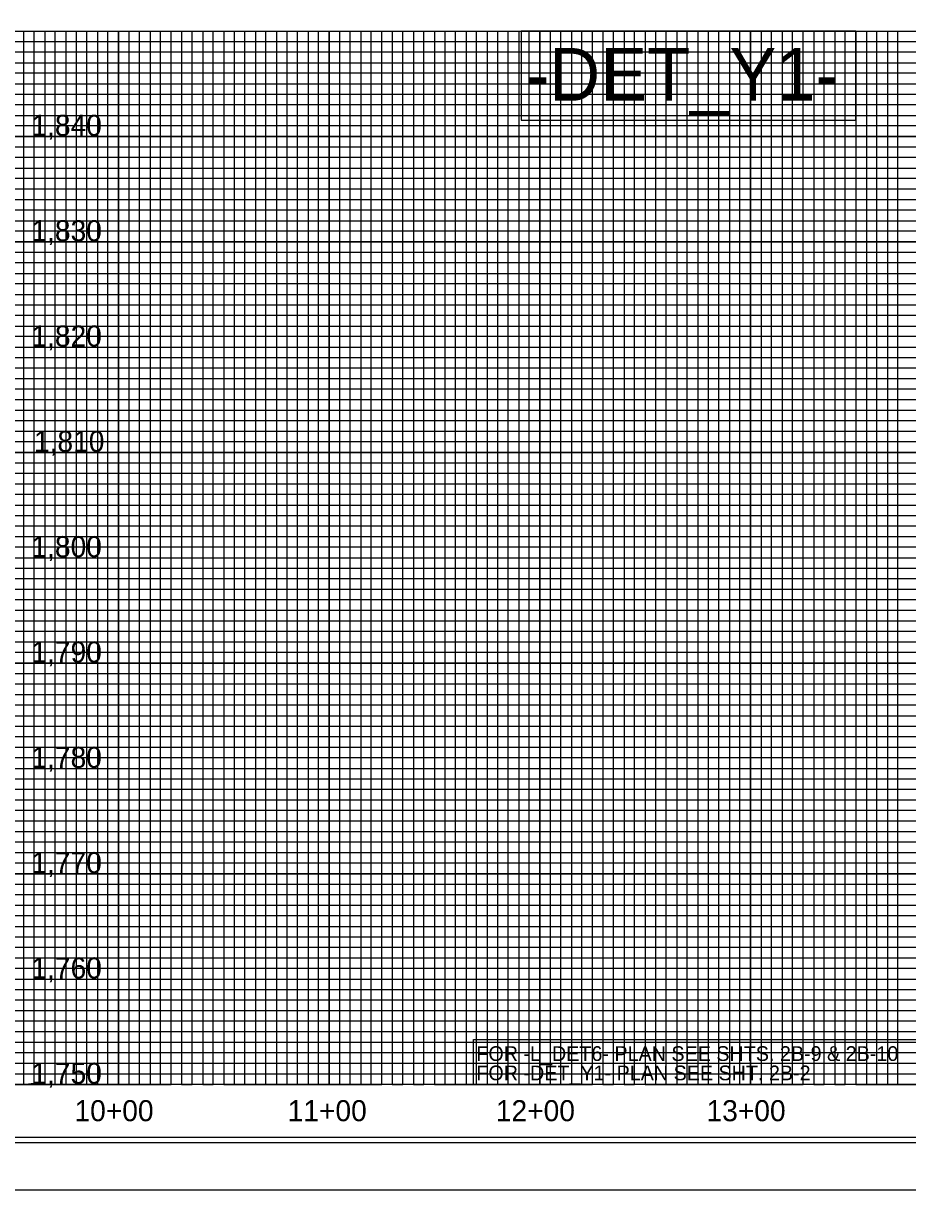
# Model space of a CAD drawing. Extents: x 497599 to 513368, y 404140 to 482942.
# Drawn here: x 506714 to 507133, y 438761 to 439315 of the extents above; entities that cross this region are included whole.
import ezdxf

# ---------------------------------------------------------------- set-up
doc = ezdxf.new("R2010")
doc.units = 0
for name, color, linetype in [('Exist Vertical Profile Vertical Axis Label', 7, 'Continuous'), ('Old_Level_1', 7, 'Continuous'), ('Prop Grid Mask', 7, 'Continuous'), ('Sheet Cutting Line CELL', 7, 'Continuous'), ('Sheet Data Field CELL', 7, 'Continuous'), ('Sheet DOT Grid CELL', 7, 'Continuous'), ('Sheet Layout Profile Border Port 2', 7, 'Continuous'), ('Sheet Plot Border Inside CELL', 7, 'Continuous'), ('Sheet Plot Border Outside CELL', 7, 'Continuous'), ('Sheet Profile CELL', 7, 'Continuous'), ('Sheet Profile Grid Major CELL', 7, 'Continuous'), ('Sheet Profile Grid Middle CELL', 7, 'Continuous'), ('Sheet Profile Grid Minor CELL', 7, 'Continuous')]:
    doc.layers.add(name, color=color, linetype=linetype)

msp = doc.modelspace()

# ---------------------------------------------------------------- linework, layer by layer
at = {"layer": 'Prop Grid Mask'}
for points in [[(507108.68, 439311.14), (506949.82, 439311.14), (506949.82, 439268.82), (507108.68, 439268.82)], [(506927.29, 438832.43), (507138.12, 438832.43), (507138.12, 438811.14), (506927.29, 438811.14)]]:
    msp.add_lwpolyline(points, close=True, dxfattribs=at)
at = {"layer": 'Sheet Cutting Line CELL'}
msp.add_line((505691.68, 438761.14), (507375.68, 438761.14), dxfattribs=at)
at = {"layer": 'Sheet DOT Grid CELL'}
for p, q in [((505858.68, 439311.14), (507358.56, 439311.14)), ((506758.68, 439311.14), (506758.68, 438811.14)), ((506808.68, 439311.14), (506808.68, 438811.14)), ((506858.68, 439311.14), (506858.68, 438811.14)), ((506908.68, 439311.14), (506908.68, 438811.14)), ((506958.68, 439311.14), (506958.68, 438811.14)), ((507008.68, 439311.14), (507008.68, 438811.14)), ((507058.68, 439311.14), (507058.68, 438811.14)), ((507108.68, 439311.14), (507108.68, 438811.14)), ((505858.68, 439261.14), (507358.56, 439261.14)), ((505858.68, 439211.14), (507358.56, 439211.14)), ((505858.68, 439161.14), (507358.56, 439161.14)), ((505858.68, 439111.14), (507358.56, 439111.14)), ((505858.68, 439061.14), (507358.56, 439061.14)), ((505858.68, 439011.14), (507358.56, 439011.14)), ((505858.68, 438961.14), (507358.56, 438961.14)), ((505858.68, 438911.14), (507358.56, 438911.14)), ((505858.68, 438861.14), (507358.56, 438861.14))]:
    msp.add_line(p, q, dxfattribs=at)
at = {"layer": 'Sheet Layout Profile Border Port 2'}
msp.add_lwpolyline([(506758.68, 439311.14), (507308.68, 439311.14), (507308.68, 438811.14), (506758.68, 438811.14)], close=True, dxfattribs=at)
at = {"layer": 'Sheet Plot Border Inside CELL'}
msp.add_lwpolyline([(505704.68, 438783.59), (507371.18, 438783.59), (507371.18, 439838.69), (505704.68, 439838.69)], close=True, dxfattribs=at)
at = {"layer": 'Sheet Plot Border Outside CELL'}
msp.add_lwpolyline([(505691.68, 438761.14), (507375.68, 438761.14), (507375.68, 439861.14), (505691.68, 439861.14)], close=True, dxfattribs=at)
at = {"layer": 'Sheet Profile CELL'}
for p, q in [((505858.68, 439311.14), (507358.68, 439311.14)), ((507358.68, 438811.14), (505858.68, 438811.14)), ((505858.68, 438786.14), (507358.68, 438786.14))]:
    msp.add_line(p, q, dxfattribs=at)
msp.add_lwpolyline([(507358.68, 439836.14), (505858.68, 439836.14), (505858.68, 438786.14), (507358.68, 438786.14)], close=True, dxfattribs=at)
at = {"layer": 'Sheet Profile Grid Major CELL'}
for p, q in [((506758.68, 439311.14), (506808.68, 439311.14)), ((506758.68, 439311.14), (506808.68, 439311.14)), ((506858.68, 439311.14), (506908.68, 439311.14)), ((506858.68, 439311.14), (506908.68, 439311.14)), ((506958.68, 439311.14), (507008.68, 439311.14)), ((506958.68, 439311.14), (507008.68, 439311.14)), ((507058.68, 439311.14), (507108.68, 439311.14)), ((507058.68, 439311.14), (507108.68, 439311.14)), ((507052.65, 438811.14), (507052.65, 438811.14))]:
    msp.add_line(p, q, dxfattribs=at)
for points in [[(506708.68, 438811.14), (506758.68, 438811.14), (506758.68, 439311.14), (506808.68, 439311.14), (506808.68, 438811.14), (506858.68, 438811.14), (506858.68, 439311.14), (506908.68, 439311.14), (506908.68, 438811.14), (506958.68, 438811.14), (506958.68, 439311.14), (507008.68, 439311.14), (507008.68, 438811.14), (507058.68, 438811.14), (507058.68, 439311.14), (507108.68, 439311.14), (507108.68, 438811.14), (507158.68, 438811.14)], [(507358.68, 439261.14), (505858.68, 439261.14)], [(507358.68, 439211.14), (505858.68, 439211.14), (505858.68, 439161.14), (507358.68, 439161.14)], [(507358.68, 439111.14), (505858.68, 439111.14), (505858.68, 439061.14), (507358.68, 439061.14)], [(507358.68, 439011.14), (505858.68, 439011.14), (505858.68, 438961.14), (507358.68, 438961.14)], [(507358.68, 438911.14), (505858.68, 438911.14), (505858.68, 438911.14), (505858.68, 438861.14), (507358.68, 438861.14)], [(507358.68, 438811.14), (505858.68, 438811.14)]]:
    msp.add_lwpolyline(points, dxfattribs=at)
at = {"layer": 'Sheet Profile Grid Middle CELL'}
for points in [[(506683.68, 439311.14), (506733.68, 439311.14), (506733.68, 438811.14), (506783.68, 438811.14), (506783.68, 439311.14), (506833.68, 439311.14), (506833.68, 438811.14), (506883.68, 438811.14), (506883.68, 439311.14), (506933.68, 439311.14), (506933.68, 438811.14), (506983.68, 438811.14), (506983.68, 439311.14), (507033.68, 439311.14), (507033.68, 438811.14), (507083.68, 438811.14), (507083.68, 439311.14), (507133.68, 439311.14)], [(505858.68, 439286.14), (507358.68, 439286.14)], [(507358.68, 439236.14), (505858.68, 439236.14), (505858.68, 439186.14), (507358.68, 439186.14)], [(507358.68, 439136.14), (505858.68, 439136.14), (505858.68, 439086.14), (507358.68, 439086.14)], [(507358.68, 439036.14), (505858.68, 439036.14), (505858.68, 438986.14), (507358.68, 438986.14)], [(507358.68, 438936.14), (505858.68, 438936.14), (505858.68, 438886.14), (507358.68, 438886.14)], [(507358.68, 438836.14), (505858.68, 438836.14)]]:
    msp.add_lwpolyline(points, dxfattribs=at)
at = {"layer": 'Sheet Profile Grid Minor CELL'}
for p, q in [((505908.68, 439306.14), (507308.68, 439306.14)), ((507308.68, 439301.14), (505908.68, 439301.14)), ((505908.68, 439296.14), (507308.68, 439296.14)), ((507308.68, 439291.14), (505908.68, 439291.14)), ((505908.68, 439281.14), (507308.68, 439281.14)), ((507308.68, 439276.14), (505908.68, 439276.14)), ((505908.68, 439271.14), (507308.68, 439271.14)), ((507308.68, 439266.14), (505908.68, 439266.14)), ((505908.68, 439256.14), (507308.68, 439256.14)), ((507308.68, 439251.14), (505908.68, 439251.14)), ((505908.68, 439246.14), (507308.68, 439246.14)), ((507308.68, 439241.14), (505908.68, 439241.14)), ((505908.68, 439231.14), (507308.68, 439231.14)), ((507308.68, 439226.14), (505908.68, 439226.14)), ((505908.68, 439221.14), (507308.68, 439221.14)), ((507308.68, 439216.14), (505908.68, 439216.14)), ((505908.68, 439206.14), (507308.68, 439206.14)), ((507308.68, 439201.14), (505908.68, 439201.14)), ((505908.68, 439196.14), (507308.68, 439196.14)), ((507308.68, 439191.14), (505908.68, 439191.14)), ((505908.68, 439181.14), (507308.68, 439181.14)), ((507308.68, 439176.14), (505908.68, 439176.14)), ((505908.68, 439171.14), (507308.68, 439171.14)), ((507308.68, 439166.14), (505908.68, 439166.14)), ((505908.68, 439156.14), (507308.68, 439156.14)), ((507308.68, 439151.14), (505908.68, 439151.14)), ((505908.68, 439146.14), (507308.68, 439146.14)), ((507308.68, 439141.14), (505908.68, 439141.14)), ((505908.68, 439131.14), (507308.68, 439131.14)), ((507308.68, 439126.14), (505908.68, 439126.14)), ((505908.68, 439121.14), (507308.68, 439121.14)), ((507308.68, 439116.14), (505908.68, 439116.29)), ((505908.68, 439106.14), (507308.68, 439106.14)), ((507308.68, 439101.14), (505908.68, 439101.14)), ((505908.68, 439096.14), (507308.68, 439096.14)), ((507308.68, 439091.14), (505908.68, 439091.14)), ((505908.68, 439081.14), (507308.68, 439081.14)), ((507308.68, 439076.14), (505908.68, 439076.14)), ((505908.68, 439071.14), (507308.68, 439071.14)), ((507308.68, 439066.14), (505908.68, 439066.14)), ((505908.68, 439056.14), (507308.68, 439056.14)), ((507308.68, 439051.14), (505908.68, 439051.14)), ((505908.68, 439046.14), (507308.68, 439046.14)), ((507308.68, 439041.14), (505908.68, 439041.14)), ((505908.68, 439031.14), (507308.68, 439031.14)), ((507308.68, 439026.14), (505908.68, 439026.14)), ((505908.68, 439021.14), (507308.68, 439021.14)), ((507308.68, 439016.14), (505908.68, 439016.14)), ((505908.68, 439006.14), (507308.68, 439006.14)), ((507308.68, 439001.14), (505908.68, 439001.14)), ((505908.68, 438996.14), (507308.68, 438996.14)), ((507308.68, 438991.14), (505908.68, 438991.14)), ((505908.68, 438981.14), (507308.68, 438981.14)), ((507308.68, 438976.14), (505908.68, 438976.14)), ((505908.68, 438971.14), (507308.68, 438971.14)), ((507308.68, 438966.14), (505908.68, 438966.14)), ((505908.68, 438956.14), (507308.68, 438956.14)), ((507308.68, 438951.14), (505908.68, 438951.14)), ((505908.68, 438946.14), (507308.68, 438946.14)), ((507308.68, 438941.14), (505908.68, 438941.14)), ((505908.68, 438931.14), (507308.68, 438931.14)), ((507308.68, 438926.14), (505908.68, 438926.14)), ((505908.68, 438921.14), (507308.68, 438921.14)), ((507308.68, 438916.14), (505908.68, 438916.14)), ((505908.68, 438906.14), (507308.68, 438906.14)), ((507308.68, 438901.14), (505908.68, 438901.14)), ((505908.68, 438896.14), (507308.68, 438896.14)), ((507308.68, 438891.14), (505908.68, 438891.14)), ((505908.68, 438881.14), (507308.68, 438881.14)), ((507308.68, 438876.14), (505908.68, 438876.14)), ((505908.68, 438871.14), (507308.68, 438871.14)), ((507308.68, 438866.14), (505908.68, 438866.14)), ((505908.68, 438856.14), (507308.68, 438856.14)), ((507308.68, 438851.14), (505908.68, 438851.14)), ((505908.68, 438846.14), (507308.68, 438846.14)), ((507308.68, 438841.14), (505908.68, 438841.14)), ((505908.68, 438831.14), (507308.68, 438831.14)), ((507308.68, 438826.14), (505908.68, 438826.14)), ((505908.68, 438821.14), (507308.68, 438821.14)), ((505908.68, 438816.14), (507308.68, 438816.14))]:
    msp.add_line(p, q, dxfattribs=at)
for points in [[(506703.68, 439311.14), (506713.68, 439311.14), (506713.68, 438811.14), (506718.38, 438811.69), (506718.68, 438811.14), (506718.68, 439311.14), (506723.68, 439311.14), (506723.68, 438811.14), (506728.68, 438811.14), (506728.68, 439311.14), (506738.68, 439311.14), (506738.68, 438811.14), (506743.68, 438811.14)], [(506743.68, 438811.14), (506743.68, 439311.14), (506748.68, 439311.14), (506748.68, 438811.14), (506753.68, 438811.14), (506753.68, 439311.14), (506763.68, 439311.14), (506763.68, 438811.14), (506768.68, 438811.14), (506768.68, 439311.14), (506773.68, 439311.14), (506773.68, 438811.14), (506778.68, 438811.14), (506778.68, 439311.14), (506788.68, 439311.14), (506788.68, 438811.14), (506793.68, 438811.14), (506793.68, 439311.14), (506798.68, 439311.14), (506798.68, 438811.14), (506803.68, 438811.14), (506803.68, 439311.14), (506813.68, 439311.14), (506813.68, 438811.14), (506818.68, 438811.14), (506818.68, 439311.14), (506823.68, 439311.14), (506823.68, 438811.14), (506828.68, 438811.14), (506828.68, 439311.14), (506838.68, 439311.14), (506838.68, 438811.14), (506843.68, 438811.14), (506843.68, 439311.14), (506848.68, 439311.14), (506848.68, 438811.14), (506853.68, 438811.14), (506853.68, 439311.14), (506863.68, 439311.14), (506863.68, 438811.14), (506868.68, 438811.14), (506868.68, 439311.14), (506873.68, 439311.14), (506873.68, 438811.14), (506878.68, 438811.14), (506878.68, 439311.14), (506888.68, 439311.14), (506888.68, 438811.14), (506893.68, 438811.14), (506893.68, 439311.14), (506898.68, 439311.14), (506898.68, 438811.14), (506903.68, 438811.14), (506903.68, 439311.14), (506913.68, 439311.14), (506913.68, 438811.14), (506918.68, 438811.14), (506918.68, 439311.14), (506923.68, 439311.14), (506923.68, 438811.14), (506928.68, 438811.14), (506928.68, 439311.14), (506938.68, 439311.14), (506938.68, 438811.14), (506943.68, 438811.14), (506943.68, 439311.14), (506948.68, 439311.14), (506948.68, 438811.14), (506953.68, 438811.14), (506953.68, 439311.14), (506963.68, 439311.14), (506963.68, 438811.14), (506968.68, 438811.14), (506968.68, 439311.14), (506973.68, 439311.14), (506973.68, 438811.14), (506978.68, 438811.14), (506978.68, 439311.14), (506988.68, 439311.14), (506988.68, 438811.14), (506993.68, 438811.14), (506993.68, 439311.14), (506998.68, 439311.14), (506998.68, 438811.14), (507003.68, 438811.14), (507003.68, 439311.14), (507013.68, 439311.14), (507013.68, 438811.14), (507018.68, 438811.14), (507018.68, 439311.14), (507023.68, 439311.14), (507023.68, 438811.14), (507028.68, 438811.14), (507028.68, 439311.14), (507038.68, 439311.14), (507038.68, 438811.14), (507043.68, 438811.14), (507043.68, 439311.14), (507048.68, 439311.14), (507048.68, 438811.14)], [(507048.68, 438811.14), (507053.68, 438811.14), (507053.68, 439311.14), (507063.68, 439311.14), (507063.68, 438811.14), (507068.68, 438811.14), (507068.68, 439311.14), (507073.68, 439311.14), (507073.68, 438811.14), (507078.68, 438811.14), (507078.68, 439311.14), (507088.68, 439311.14), (507088.68, 438811.14), (507093.68, 438811.14), (507093.68, 439311.14), (507098.68, 439311.14), (507098.68, 438811.14), (507103.68, 438811.14), (507103.68, 439311.14), (507113.68, 439311.14), (507113.68, 438811.14), (507118.68, 438811.14), (507118.68, 439311.14), (507123.68, 439311.14), (507123.68, 438811.14), (507128.68, 438811.14), (507128.68, 439311.14), (507138.68, 439311.14)]]:
    msp.add_lwpolyline(points, dxfattribs=at)

# ---------------------------------------------------------------- texts
at = {"layer": 'Exist Vertical Profile Vertical Axis Label'}
for s, p in [('1,840', (506717.37, 439261.39)), ('1,830', (506717.37, 439211.39)), ('1,820', (506717.37, 439161.39)), ('1,810', (506718.57, 439111.39)), ('1,800', (506717.37, 439061.39)), ('1,790', (506717.37, 439011.39)), ('1,780', (506717.37, 438961.39)), ('1,770', (506717.37, 438911.39)), ('1,760', (506717.37, 438861.39)), ('1,750', (506717.37, 438811.39)), ('10+00', (506737.81, 438793.64)), ('11+00', (506839, 438793.64)), ('12+00', (506937.81, 438793.64)), ('13+00', (507037.81, 438793.64))]:
    msp.add_text(s, height=10, dxfattribs=at).set_placement(p)
at = {"layer": 'Old_Level_1'}
msp.add_text('-DET_Y1-', height=25, dxfattribs=at).set_placement((506952.06, 439278.11))
at = {"layer": 'Sheet Data Field CELL'}
for s, p in [('FOR -L_DET6- PLAN SEE SHTS. 2B-9 & 2B-10', (506928.57, 438822.25)), ('FOR -DET_Y1- PLAN SEE SHT. 2B-2', (506928.57, 438813.07))]:
    msp.add_text(s, height=7, rotation=360, dxfattribs=at).set_placement(p)

doc.saveas('drawing.dxf')
